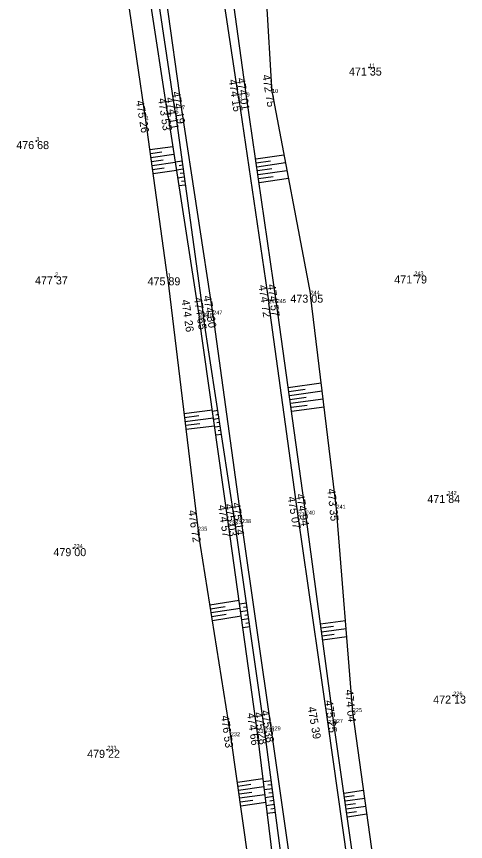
# Model space of a CAD drawing. Extents: x -559180 to -551373, y -1076947 to -1072071.
# Drawn here: x -553828.2 to -553772.2, y -1075619.3 to -1075516.2 of the extents above; entities that cross this region are included whole.
import ezdxf

# ---------------------------------------------------------------- set-up
doc = ezdxf.new("R2010")
doc.units = 0
for name, color, linetype in [('17_KOMUNIKACE', 7, 'Continuous'), ('1_VODA_ZN', 7, 'Continuous'), ('26_SRAFY', 7, 'Continuous'), ('27_HRANA_PATA', 7, 'Continuous'), ('3_BODY', 7, 'Continuous'), ('6_VYSKY', 7, 'Continuous')]:
    doc.layers.add(name, color=color, linetype=linetype)

# ---------------------------------------------------------------- blocks, each defined once
blk = doc.blocks.new('T')
at = {"layer": '6_VYSKY'}
blk.add_circle((0, 0), 0.05, dxfattribs=at)
blk = doc.blocks.new('POINT_DISPLAY')
blk.add_line((0, 0), (0, 0))

msp = doc.modelspace()

# ---------------------------------------------------------------- linework, layer by layer
at = {"layer": '17_KOMUNIKACE'}
for p, q in [((-553807.54, -1075527.85), (-553810.14, -1075509.53)), ((-553800.44, -1075526.58), (-553803.03, -1075509.45)), ((-553800.44, -1075526.58), (-553796.72, -1075552.06)), ((-553803.65, -1075553.49), (-553807.54, -1075527.85)), ((-553793.04, -1075578.67), (-553796.72, -1075552.06)), ((-553800.06, -1075579.53), (-553803.65, -1075553.49)), ((-553789.3, -1075604.65), (-553793.04, -1075578.67)), ((-553796.37, -1075605.42), (-553800.06, -1075579.53)), ((-553792.33, -1075633.71), (-553796.37, -1075605.42)), ((-553785.33, -1075632.48), (-553789.3, -1075604.65))]:
    msp.add_line(p, q, dxfattribs=at)
at = {"layer": '26_SRAFY'}
for p, q in [((-553808.69, -1075532.503), (-553811.552, -1075532.902)), ((-553810.048, -1075533.197), (-553811.483, -1075533.397)), ((-553808.538, -1075533.491), (-553811.414, -1075533.893)), ((-553809.903, -1075534.187), (-553811.344, -1075534.388)), ((-553808.398, -1075534.397), (-553807.538, -1075534.279)), ((-553794.822, -1075533.542), (-553798.339, -1075534.052)), ((-553796.498, -1075534.29), (-553798.267, -1075534.547)), ((-553808.385, -1075534.48), (-553811.275, -1075534.883)), ((-553809.758, -1075535.176), (-553811.206, -1075535.378)), ((-553808.245, -1075535.385), (-553807.402, -1075535.269)), ((-553807.896, -1075534.832), (-553807.47, -1075534.774)), ((-553794.635, -1075534.525), (-553798.195, -1075535.042)), ((-553796.332, -1075535.277), (-553798.123, -1075535.537)), ((-553808.233, -1075535.468), (-553811.137, -1075535.873)), ((-553808.093, -1075536.374), (-553807.266, -1075536.26)), ((-553807.752, -1075535.822), (-553807.334, -1075535.765)), ((-553794.447, -1075535.509), (-553798.052, -1075536.031)), ((-553796.167, -1075536.263), (-553797.98, -1075536.526)), ((-553807.94, -1075537.362), (-553807.13, -1075537.251)), ((-553807.607, -1075536.812), (-553807.198, -1075536.755)), ((-553794.26, -1075536.492), (-553797.908, -1075537.021)), ((-553790.16, -1075562.056), (-553794.273, -1075562.623)), ((-553792.152, -1075562.835), (-553794.204, -1075563.118)), ((-553790.039, -1075563.049), (-553794.136, -1075563.613)), ((-553792.024, -1075563.827), (-553794.068, -1075564.109)), ((-553789.919, -1075564.042), (-553794, -1075564.604)), ((-553791.895, -1075564.819), (-553793.931, -1075565.099)), ((-553789.799, -1075565.035), (-553793.863, -1075565.595)), ((-553803.752, -1075565.441), (-553807.29, -1075565.865)), ((-553805.456, -1075566.149), (-553807.231, -1075566.361)), ((-553803.738, -1075565.541), (-553803.068, -1075565.439)), ((-553803.33, -1075565.985), (-553802.992, -1075565.933)), ((-553803.611, -1075566.432), (-553807.171, -1075566.858)), ((-553805.327, -1075567.14), (-553807.112, -1075567.354)), ((-553803.597, -1075566.532), (-553802.916, -1075566.427)), ((-553803.184, -1075566.974), (-553802.84, -1075566.921)), ((-553803.471, -1075567.422), (-553807.053, -1075567.851)), ((-553803.457, -1075567.522), (-553802.764, -1075567.415)), ((-553803.038, -1075567.963), (-553802.688, -1075567.91)), ((-553803.317, -1075568.512), (-553802.612, -1075568.404)), ((-553800.419, -1075589.19), (-553804.061, -1075589.771)), ((-553802.167, -1075589.975), (-553803.983, -1075590.265)), ((-553800.361, -1075589.605), (-553799.485, -1075589.481)), ((-553799.854, -1075590.038), (-553799.415, -1075589.976)), ((-553800.282, -1075590.181), (-553803.904, -1075590.758)), ((-553802.019, -1075590.964), (-553803.825, -1075591.252)), ((-553800.224, -1075590.596), (-553799.344, -1075590.471)), ((-553799.715, -1075591.028), (-553799.274, -1075590.966)), ((-553800.145, -1075591.172), (-553803.747, -1075591.746)), ((-553800.087, -1075591.586), (-553799.204, -1075591.461)), ((-553799.576, -1075592.019), (-553799.133, -1075591.956)), ((-553787.141, -1075591.744), (-553790.255, -1075592.162)), ((-553799.95, -1075592.577), (-553799.063, -1075592.451)), ((-553788.645, -1075592.45), (-553790.189, -1075592.657)), ((-553787.062, -1075592.743), (-553790.122, -1075593.153)), ((-553788.539, -1075593.445), (-553790.056, -1075593.648)), ((-553786.982, -1075593.741), (-553789.989, -1075594.144)), ((-553797.428, -1075611.479), (-553800.625, -1075611.935)), ((-553797.387, -1075611.818), (-553796.387, -1075611.686)), ((-553798.961, -1075612.203), (-553800.554, -1075612.43)), ((-553797.307, -1075612.471), (-553800.484, -1075612.925)), ((-553797.266, -1075612.811), (-553796.256, -1075612.678)), ((-553796.824, -1075612.248), (-553796.322, -1075612.182)), ((-553798.83, -1075613.194), (-553800.413, -1075613.42)), ((-553797.185, -1075613.464), (-553800.342, -1075613.915)), ((-553797.145, -1075613.804), (-553796.125, -1075613.669)), ((-553796.698, -1075613.24), (-553796.191, -1075613.173)), ((-553784.867, -1075612.944), (-553787.332, -1075613.299)), ((-553786.029, -1075613.616), (-553787.26, -1075613.794)), ((-553798.698, -1075614.185), (-553800.271, -1075614.41)), ((-553797.064, -1075614.457), (-553800.201, -1075614.905)), ((-553797.023, -1075614.796), (-553795.994, -1075614.66)), ((-553796.572, -1075614.232), (-553796.06, -1075614.165)), ((-553784.73, -1075613.934), (-553787.189, -1075614.289)), ((-553785.889, -1075614.607), (-553787.118, -1075614.784)), ((-553796.902, -1075615.789), (-553795.863, -1075615.652)), ((-553796.446, -1075615.224), (-553795.929, -1075615.156)), ((-553784.592, -1075614.925), (-553787.046, -1075615.279)), ((-553785.749, -1075615.597), (-553786.975, -1075615.774)), ((-553784.454, -1075615.915), (-553786.903, -1075616.268))]:
    msp.add_line(p, q, dxfattribs=at)
at = {"layer": '27_HRANA_PATA'}
for p, q in [((-553796.3, -1075525.78), (-553797.35, -1075507.74)), ((-553812.07, -1075529.19), (-553815, -1075508.9)), ((-553809.27, -1075528.75), (-553812.21, -1075509.4)), ((-553808.35, -1075528.37), (-553811.14, -1075509.52)), ((-553799.47, -1075526.25), (-553801.83, -1075509.28)), ((-553796.3, -1075525.78), (-553791.5, -1075550.99)), ((-553795.73, -1075552.04), (-553799.47, -1075526.25)), ((-553809.33, -1075548.82), (-553812.07, -1075529.19)), ((-553809.27, -1075528.75), (-553805.4, -1075553.81)), ((-553808.35, -1075528.37), (-553804.86, -1075553.78)), ((-553809.33, -1075548.82), (-553805.54, -1075580.49)), ((-553788.26, -1075577.74), (-553791.5, -1075550.99)), ((-553792.09, -1075578.47), (-553795.73, -1075552.04)), ((-553801.73, -1075579.71), (-553805.4, -1075553.81)), ((-553800.89, -1075579.61), (-553804.86, -1075553.78)), ((-553788.6, -1075604.51), (-553792.09, -1075578.47)), ((-553786.23, -1075603.15), (-553788.26, -1075577.74)), ((-553798.13, -1075605.74), (-553801.73, -1075579.71)), ((-553797.19, -1075605.61), (-553800.89, -1075579.61)), ((-553801.45, -1075606.16), (-553805.54, -1075580.49)), ((-553783.25, -1075624.57), (-553786.23, -1075603.15)), ((-553784.58, -1075632.37), (-553788.6, -1075604.51)), ((-553797.34, -1075634.93), (-553801.45, -1075606.16)), ((-553794.64, -1075634.29), (-553798.13, -1075605.74)), ((-553793.44, -1075633.99), (-553797.19, -1075605.61))]:
    msp.add_line(p, q, dxfattribs=at)

# ---------------------------------------------------------------- block references
at = {"layer": '1_VODA_ZN'}
for p in [(-553784.19, -1075522.61), (-553796.3, -1075525.78), (-553800.44, -1075526.58), (-553799.47, -1075526.25), (-553807.54, -1075527.85), (-553812.07, -1075529.19), (-553809.27, -1075528.75), (-553808.35, -1075528.37), (-553825.72, -1075531.8), (-553823.38, -1075548.71), (-553778.54, -1075548.59), (-553809.33, -1075548.82), (-553791.5, -1075550.99), (-553796.72, -1075552.06), (-553795.73, -1075552.04), (-553805.4, -1075553.81), (-553804.86, -1075553.78), (-553803.65, -1075553.49), (-553796.75, -1075553.25), (-553774.41, -1075576.02), (-553793.04, -1075578.67), (-553792.09, -1075578.47), (-553788.26, -1075577.74), (-553801.73, -1075579.71), (-553800.89, -1075579.61), (-553800.06, -1075579.53), (-553805.54, -1075580.49), (-553821.08, -1075582.66), (-553773.68, -1075601.08), (-553786.23, -1075603.15), (-553796.37, -1075605.42), (-553789.3, -1075604.65), (-553788.6, -1075604.51), (-553801.45, -1075606.16), (-553798.13, -1075605.74), (-553797.19, -1075605.61), (-553816.87, -1075607.86)]:
    msp.add_blockref('POINT_DISPLAY', p, dxfattribs=at)
at = {"layer": '6_VYSKY'}
for p in [(-553784.19, -1075522.61), (-553784.19, -1075522.61), (-553825.72, -1075531.8), (-553825.72, -1075531.8), (-553823.38, -1075548.71), (-553823.38, -1075548.71), (-553778.54, -1075548.59), (-553778.54, -1075548.59), (-553774.41, -1075576.02), (-553774.41, -1075576.02), (-553821.08, -1075582.66), (-553821.08, -1075582.66), (-553773.68, -1075601.08), (-553773.68, -1075601.08), (-553816.87, -1075607.86), (-553816.87, -1075607.86)]:
    msp.add_blockref('T', p, dxfattribs=at)

# ---------------------------------------------------------------- texts
at = {"layer": '3_BODY'}
for s, p in [('11', (-553784.19, -1075522.61)), ('8', (-553800.44, -1075526.58)), ('9', (-553799.47, -1075526.25)), ('10', (-553796.3, -1075525.78)), ('6', (-553808.35, -1075528.37)), ('7', (-553807.54, -1075527.85)), ('4', (-553812.07, -1075529.19)), ('5', (-553809.27, -1075528.75)), ('3', (-553825.72, -1075531.8)), ('2', (-553823.38, -1075548.71)), ('1', (-553809.33, -1075548.82)), ('243', (-553778.54, -1075548.59)), ('244', (-553791.5, -1075550.99)), ('246', (-553796.72, -1075552.06)), ('245', (-553795.73, -1075552.04)), ('249', (-553805.4, -1075553.81)), ('248', (-553804.86, -1075553.78)), ('247', (-553803.65, -1075553.49)), ('242', (-553774.41, -1075576.02)), ('241', (-553788.26, -1075577.74)), ('239', (-553793.04, -1075578.67)), ('240', (-553792.09, -1075578.47)), ('236', (-553801.73, -1075579.71)), ('237', (-553800.89, -1075579.61)), ('238', (-553800.06, -1075579.53)), ('235', (-553805.54, -1075580.49)), ('234', (-553821.08, -1075582.66)), ('226', (-553773.68, -1075601.08)), ('225', (-553786.23, -1075603.15)), ('228', (-553789.3, -1075604.65)), ('227', (-553788.6, -1075604.51)), ('231', (-553798.13, -1075605.74)), ('230', (-553797.19, -1075605.61)), ('229', (-553796.37, -1075605.42)), ('232', (-553801.45, -1075606.16)), ('233', (-553816.87, -1075607.86))]:
    msp.add_text(s, height=0.5, dxfattribs=at).set_placement(p)
at = {"layer": '6_VYSKY'}
for s, p in [('471 35', (-553786.695, -1075523.61)), ('476 68', (-553828.225, -1075532.8)), ('477 37', (-553825.885, -1075549.71)), ('475 89', (-553811.835, -1075549.82)), ('471 79', (-553781.045, -1075549.59)), ('473 05', (-553794.005, -1075551.99)), ('471 84', (-553776.915, -1075577.02)), ('479 00', (-553823.585, -1075583.66)), ('472 13', (-553776.185, -1075602.08)), ('479 22', (-553819.375, -1075608.86))]:
    msp.add_text(s, height=1, dxfattribs=at).set_placement(p)
for s, rotation, p in [('474 01', 278.62709, (-553800.684, -1075523.966)), ('472 75', 279.40868, (-553797.529, -1075523.575)), ('474 15', 278.67086, (-553801.718, -1075524.153)), ('474 19', 279.1927, (-553808.77, -1075525.684)), ('475 26', 279.74944, (-553813.3, -1075526.808)), ('473 53', 278.82127, (-553810.531, -1075526.499)), ('474 11', 280.02647, (-553809.587, -1075526.407)), ('474 72', 278.54424, (-553797.982, -1075549.838)), ('474 57', 277.66643, (-553796.871, -1075549.738)), ('474 26', 278.36071, (-553807.617, -1075551.674)), ('474 65', 278.76286, (-553806.052, -1075551.384)), ('474 80', 279.59344, (-553804.885, -1075551.183)), ('473 35', 275.95604, (-553789.398, -1075575.263)), ('475 07', 279.66258, (-553794.359, -1075576.283)), ('474 94', 279.43874, (-553793.292, -1075575.937)), ('474 57', 278.57724, (-553803.046, -1075577.322)), ('475 03', 278.48231, (-553802.195, -1075577.188)), ('475 14', 277.31902, (-553801.266, -1075577.033)), ('476 72', 278.48728, (-553806.762, -1075577.976)), ('474 04', 275.18331, (-553787.169, -1075600.375)), ('475 25', 277.46139, (-553789.709, -1075601.73)), ('474 66', 277.95663, (-553799.428, -1075603.307)), ('475 28', 279.32129, (-553798.531, -1075603.229)), ('475 38', 279.54184, (-553797.667, -1075602.986)), ('475 39', 279.7558, (-553791.847, -1075602.548)), ('476 53', 278.01388, (-553802.675, -1075603.627))]:
    msp.add_text(s, height=1, rotation=rotation, dxfattribs=at).set_placement(p)

doc.saveas('drawing.dxf')
